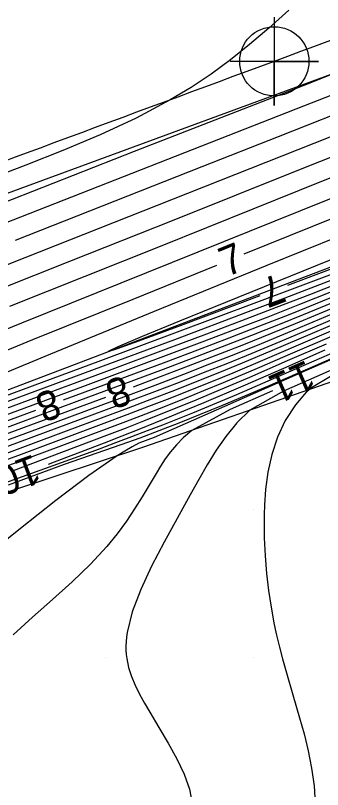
# Model space of a CAD drawing. Extents: x 2602990 to 2605851, y 618069 to 619180.
# Drawn here: x 2603323.9 to 2603344.7, y 618361.1 to 618413.5 of the extents above; entities that cross this region are included whole.
import ezdxf

# ---------------------------------------------------------------- set-up
doc = ezdxf.new("R2010")
doc.units = 0
for name, color, linetype in [('DTM Contours Major', 7, 'Continuous'), ('DTM Contours Major Text', 7, 'Continuous'), ('DTM Contours Minor', 7, 'Continuous'), ('DTM Contours Minor Text', 7, 'Continuous'), ('Exist DTM Breakline', 7, 'Continuous'), ('Exist DTM Crownline', 7, 'Continuous'), ('Exist DTM Drainline', 7, 'Continuous'), ('Exist DTM QL2 LIDAR Elevation Point', 7, 'Continuous'), ('Exist Roads EOP', 7, 'Continuous'), ('Exist Roads EOP Cogo Point CELL', 7, 'Continuous'), ('PH Exist DTM Breakline', 7, 'Continuous')]:
    doc.layers.add(name, color=color, linetype=linetype)

# ---------------------------------------------------------------- blocks, each defined once
blk = doc.blocks.new('EXIST ROADS EOP COGO POINT')
at = {"layer": 'Exist Roads EOP Cogo Point CELL'}
blk.add_lwpolyline([(0, 0.06), (0, -0.06), (0, 0), (0.06, 0), (-0.06, 0)], dxfattribs=at)
blk.add_circle((0, 0), 0.0469, dxfattribs=at)

msp = doc.modelspace()

# ---------------------------------------------------------------- linework, layer by layer
at = {"layer": 'DTM Contours Major'}
for points in [[(2603413.545, 618431.919), (2603412.996, 618431.681), (2603409.631, 618430.243), (2603406.411, 618428.892), (2603404.635, 618428.163), (2603402.929, 618427.472), (2603397.939, 618425.471), (2603396.224, 618424.775), (2603393.341, 618423.584), (2603390.362, 618422.333), (2603387.382, 618421.067), (2603378.36, 618417.204), (2603374.888, 618415.735), (2603371.983, 618414.523), (2603369.421, 618413.467), (2603366.184, 618412.15), (2603362.493, 618410.666), (2603360.498, 618409.871), (2603355.313, 618407.823), (2603347.349, 618404.69), (2603343.063, 618402.99), (2603334.617, 618399.609), (2603327.541, 618396.809), (2603322.626, 618394.861)], [(2603327.142, 618387.436), (2603329.882, 618388.446), (2603334.103, 618390.016), (2603336.235, 618390.819), (2603338.358, 618391.628), (2603340.454, 618392.438), (2603342.502, 618393.244), (2603345.343, 618394.387), (2603348.24, 618395.558), (2603349.768, 618396.167), (2603351.382, 618396.8), (2603354.411, 618397.96), (2603357.65, 618399.168), (2603360.984, 618400.389), (2603364.298, 618401.584), (2603367.476, 618402.714), (2603370.402, 618403.744), (2603377.465, 618406.199), (2603378.885, 618406.7)], [(2603321.928, 618381.394), (2603325.861, 618382.792), (2603329.565, 618384.129), (2603330.69, 618384.544), (2603331.775, 618384.95), (2603332.828, 618385.351), (2603333.862, 618385.751), (2603334.885, 618386.155), (2603335.909, 618386.567), (2603338.881, 618387.801), (2603341.899, 618389.097), (2603347.922, 618391.734)], [(2603232.042, 618350.596), (2603232.796, 618350.941), (2603234.02, 618351.488), (2603235.249, 618352.027), (2603236.484, 618352.559), (2603237.724, 618353.086), (2603240.316, 618354.172), (2603243.023, 618355.288), (2603245.739, 618356.391), (2603248.557, 618357.518), (2603251.681, 618358.75), (2603259.068, 618361.639), (2603269.134, 618365.569), (2603283.544, 618371.218), (2603285.941, 618372.151), (2603288.321, 618373.072), (2603290.658, 618373.969), (2603292.932, 618374.831), (2603294.547, 618375.436), (2603297.726, 618376.612), (2603305.437, 618379.437), (2603325.265, 618386.744)]]:
    msp.add_lwpolyline(points, dxfattribs=at)
at = {"layer": 'DTM Contours Minor'}
for points in [[(2603403.118, 618431.883), (2603402.833, 618431.716), (2603401.509, 618431.051), (2603400.138, 618430.437), (2603398.705, 618429.837), (2603396.601, 618428.974), (2603389.756, 618426.194), (2603387.413, 618425.235), (2603385.098, 618424.275), (2603383.059, 618423.417), (2603381.096, 618422.58), (2603379.234, 618421.777), (2603375.917, 618420.331), (2603372.342, 618418.768), (2603370.744, 618418.086), (2603369.125, 618417.415), (2603367.476, 618416.749), (2603366.161, 618416.225), (2603363.212, 618415.062), (2603355.846, 618412.179), (2603342.883, 618407.119), (2603323.073, 618399.352)], [(2603404.805, 618429.792), (2603402.356, 618428.763), (2603397.015, 618426.54), (2603393.763, 618425.171), (2603390.363, 618423.726), (2603383.658, 618420.855), (2603377.118, 618418.051), (2603373.608, 618416.562), (2603370.947, 618415.449), (2603368.133, 618414.295), (2603365.49, 618413.229), (2603362.398, 618411.996), (2603356.695, 618409.75), (2603347.476, 618406.133), (2603343.027, 618404.375), (2603335.553, 618401.401), (2603324.512, 618397.047), (2603321.717, 618395.941)], [(2603420.115, 618429.811), (2603414.444, 618427.466), (2603412.4, 618426.631), (2603410.273, 618425.78), (2603407.575, 618424.729), (2603404.796, 618423.669), (2603399.182, 618421.553), (2603396.445, 618420.513), (2603393.816, 618419.495), (2603391.861, 618418.719), (2603389.996, 618417.962), (2603388.217, 618417.228), (2603384.894, 618415.834), (2603380.738, 618414.085), (2603376.915, 618412.495), (2603372.47, 618410.663), (2603366.926, 618408.396), (2603360.741, 618405.884), (2603357.67, 618404.644), (2603353.114, 618402.816), (2603345.544, 618399.793), (2603340.999, 618397.957), (2603339.355, 618397.29)], [(2603419.344, 618427.828), (2603414.878, 618426.042), (2603413.257, 618425.399), (2603411.538, 618424.727), (2603408.592, 618423.6), (2603405.452, 618422.42), (2603399.003, 618420.016), (2603395.902, 618418.85), (2603393.023, 618417.746), (2603391.418, 618417.117), (2603389.917, 618416.517), (2603388.501, 618415.943), (2603385.862, 618414.853), (2603379.015, 618412.007), (2603373.646, 618409.794), (2603366.67, 618406.942), (2603359.531, 618404.041), (2603352.87, 618401.348), (2603345.847, 618398.525), (2603340.928, 618396.532), (2603333.274, 618393.41), (2603325.868, 618390.375), (2603313.612, 618385.304)], [(2603417.517, 618425.453), (2603414.066, 618424.14), (2603412.789, 618423.658), (2603409.595, 618422.466), (2603398.796, 618418.475), (2603395.337, 618417.183), (2603392.219, 618416), (2603391, 618415.528), (2603388.789, 618414.656), (2603386.781, 618413.846), (2603382.843, 618412.232), (2603374.157, 618408.651), (2603367.059, 618405.748), (2603358.865, 618402.415), (2603348.621, 618398.269), (2603338.121, 618394.025), (2603335.008, 618392.758), (2603332.478, 618391.718), (2603330.78, 618391.004), (2603330.166, 618390.713), (2603330.794, 618390.91), (2603332.502, 618391.528), (2603335.058, 618392.477), (2603340.472, 618394.503)], [(2603290.205, 618375.323), (2603291.172, 618375.7), (2603294.664, 618377.053), (2603299.329, 618378.84), (2603301.718, 618379.745), (2603305.614, 618381.208), (2603309.652, 618382.713), (2603313.719, 618384.22), (2603329.659, 618390.101), (2603334.868, 618392.036), (2603342.845, 618395.018), (2603349.595, 618397.548), (2603354.049, 618399.193), (2603357.917, 618400.605), (2603361.91, 618402.052), (2603365.862, 618403.476), (2603369.608, 618404.82), (2603380.777, 618408.802), (2603385.235, 618410.41), (2603388.763, 618411.704), (2603393.297, 618413.38), (2603399.856, 618415.829), (2603421.294, 618423.877)], [(2603342.346, 618395.203), (2603346.74, 618396.847), (2603349.221, 618397.769), (2603353.79, 618399.451), (2603358.304, 618401.098), (2603362.673, 618402.68), (2603366.805, 618404.166), (2603373.987, 618406.733), (2603380.77, 618409.151), (2603385.418, 618410.826), (2603388.674, 618412.017), (2603392.382, 618413.39), (2603399.188, 618415.936), (2603411.378, 618420.524), (2603420.72, 618424.055)], [(2603313.054, 618383.538), (2603329.838, 618389.732), (2603334.678, 618391.531), (2603339.689, 618393.409), (2603342.171, 618394.347), (2603346.586, 618396.033), (2603349.67, 618397.21), (2603350.771, 618397.626), (2603354.149, 618398.885), (2603357.825, 618400.235), (2603361.637, 618401.621), (2603365.425, 618402.986), (2603369.026, 618404.275), (2603374.166, 618406.1), (2603379.131, 618407.858), (2603382.195, 618408.957), (2603385.008, 618409.977), (2603388.356, 618411.209), (2603394.207, 618413.366), (2603397.184, 618414.473), (2603415.908, 618421.475)], [(2603315.864, 618384.142), (2603329.882, 618389.314), (2603334.484, 618391.024), (2603336.858, 618391.914), (2603339.233, 618392.811), (2603341.576, 618393.703), (2603343.851, 618394.58), (2603348.482, 618396.388), (2603350.993, 618397.355), (2603354.232, 618398.574), (2603357.751, 618399.874), (2603361.4, 618401.203), (2603365.029, 618402.512), (2603368.489, 618403.748), (2603372.728, 618405.247), (2603377.537, 618406.937), (2603380.566, 618408.015), (2603383.427, 618409.047), (2603386.036, 618410.004), (2603390.363, 618411.608), (2603395.133, 618413.359), (2603398.065, 618414.445), (2603411.959, 618419.632), (2603416.921, 618421.474)], [(2603380.805, 618415.486), (2603377.358, 618414.039), (2603373.024, 618412.243), (2603369.671, 618410.866), (2603364.659, 618408.825), (2603359.3, 618406.66), (2603354.671, 618404.81), (2603347.142, 618401.824), (2603343.198, 618400.245), (2603332.764, 618396.031), (2603324.278, 618392.634), (2603322.422, 618391.886)], [(2603377.805, 618415.596), (2603376.515, 618415.052), (2603372.497, 618413.38), (2603369.54, 618412.164), (2603365.443, 618410.495), (2603360.917, 618408.671), (2603358.577, 618407.737), (2603353.996, 618405.922), (2603347.242, 618403.255), (2603343.12, 618401.613), (2603333.689, 618397.82), (2603323.48, 618393.759)], [(2603365.922, 618414.765), (2603365.384, 618414.55), (2603361.367, 618412.964), (2603347.631, 618407.585), (2603341.685, 618405.245), (2603336.517, 618403.202), (2603323.851, 618398.222)], [(2603342.419, 618413.827), (2603341.064, 618412.608), (2603339.751, 618411.488), (2603338.453, 618410.454), (2603337.142, 618409.493), (2603335.793, 618408.593), (2603334.376, 618407.74), (2603332.071, 618406.519), (2603329.621, 618405.376), (2603327.099, 618404.309), (2603324.577, 618403.317), (2603322.127, 618402.396)], [(2603347.158, 618410.217), (2603346.255, 618409.847), (2603344.289, 618409.057), (2603342.462, 618408.338), (2603331.935, 618404.24), (2603319.49, 618399.375)], [(2603321.359, 618384.871), (2603328.055, 618387.337), (2603331.893, 618388.759), (2603333.912, 618389.514), (2603335.927, 618390.274), (2603337.926, 618391.039), (2603339.904, 618391.809), (2603341.851, 618392.582), (2603343.402, 618393.21), (2603348.131, 618395.148), (2603349.808, 618395.825), (2603351.574, 618396.525), (2603354.508, 618397.656), (2603357.613, 618398.82), (2603360.792, 618399.986), (2603363.948, 618401.124), (2603366.984, 618402.203), (2603369.804, 618403.192), (2603377.41, 618405.823), (2603378.785, 618406.306)], [(2603331.886, 618388.324), (2603333.72, 618389.011), (2603335.617, 618389.73), (2603337.496, 618390.452), (2603339.358, 618391.181), (2603341.204, 618391.92), (2603342.879, 618392.606), (2603348.031, 618394.742), (2603349.857, 618395.487), (2603351.771, 618396.252), (2603354.61, 618397.353), (2603357.58, 618398.471), (2603360.604, 618399.584), (2603363.602, 618400.665), (2603366.498, 618401.693), (2603369.211, 618402.641), (2603373.538, 618404.13), (2603376.116, 618405.015), (2603377.351, 618405.444), (2603378.683, 618405.911)], [(2603307.387, 618378.871), (2603325.442, 618385.504), (2603329.87, 618387.141), (2603331.717, 618387.829), (2603333.526, 618388.509), (2603335.305, 618389.186), (2603337.065, 618389.866), (2603338.814, 618390.555), (2603340.561, 618391.259), (2603342.358, 618392.001), (2603347.941, 618394.34), (2603349.916, 618395.154), (2603351.972, 618395.982), (2603354.713, 618397.051), (2603357.549, 618398.123), (2603360.418, 618399.181), (2603363.261, 618400.207), (2603366.015, 618401.183), (2603368.621, 618402.092), (2603371.763, 618403.171), (2603375.976, 618404.61), (2603377.289, 618405.064), (2603378.581, 618405.517)], [(2603321.931, 618383.339), (2603327.334, 618385.332), (2603329.882, 618386.28), (2603331.534, 618386.9), (2603333.126, 618387.503), (2603334.677, 618388.099), (2603336.206, 618388.697), (2603337.733, 618389.307), (2603339.277, 618389.937), (2603341.318, 618390.791), (2603347.794, 618393.55), (2603350.066, 618394.5), (2603352.392, 618395.449), (2603354.925, 618396.447), (2603357.488, 618397.424), (2603360.051, 618398.375), (2603362.585, 618399.291), (2603365.059, 618400.166), (2603367.444, 618400.994), (2603370.938, 618402.186), (2603375.696, 618403.798), (2603377.167, 618404.304), (2603378.379, 618404.728)], [(2603322.547, 618384.004), (2603327.504, 618385.83), (2603331.627, 618387.364), (2603333.328, 618388.006), (2603334.992, 618388.642), (2603336.635, 618389.281), (2603338.272, 618389.93), (2603339.919, 618390.598), (2603341.837, 618391.396), (2603347.862, 618393.942), (2603349.986, 618394.824), (2603352.179, 618395.714), (2603354.819, 618396.749), (2603357.519, 618397.774), (2603360.235, 618398.778), (2603362.922, 618399.749), (2603365.536, 618400.675), (2603368.032, 618401.543), (2603371.353, 618402.679), (2603374.766, 618403.84)], [(2603301.107, 618378.27), (2603328.447, 618388.349), (2603332.064, 618389.689), (2603334.292, 618390.52), (2603336.545, 618391.365), (2603338.793, 618392.218), (2603341.009, 618393.068), (2603343.165, 618393.909), (2603348.357, 618395.971), (2603349.736, 618396.513), (2603351.19, 618397.078), (2603354.319, 618398.266), (2603357.695, 618399.519), (2603361.185, 618400.794), (2603363.976, 618401.8)], [(2603320.713, 618382.011), (2603323.918, 618383.19), (2603327.021, 618384.341), (2603329.923, 618385.43), (2603331.352, 618385.972), (2603332.719, 618386.497), (2603334.044, 618387.014), (2603335.35, 618387.532), (2603336.659, 618388.062), (2603337.991, 618388.612), (2603340.291, 618389.585), (2603342.692, 618390.618), (2603345.171, 618391.692), (2603347.704, 618392.782), (2603350.267, 618393.868), (2603352.837, 618394.927), (2603355.141, 618395.843), (2603357.426, 618396.722), (2603359.687, 618397.564), (2603361.917, 618398.373), (2603362.83, 618398.696)], [(2603337.502, 618396.538), (2603331.831, 618394.237), (2603325.031, 618391.49), (2603320.312, 618389.566)], [(2603318.338, 618381.583), (2603324.287, 618383.768), (2603327.172, 618384.835), (2603329.897, 618385.853), (2603331.442, 618386.435), (2603332.923, 618387), (2603334.361, 618387.556), (2603335.778, 618388.114), (2603337.195, 618388.684), (2603338.635, 618389.275), (2603340.802, 618390.187), (2603347.551, 618393.081)], [(2603347.449, 618391.17), (2603344.196, 618389.749), (2603340.97, 618388.349), (2603337.86, 618387.03), (2603334.954, 618385.85), (2603333.606, 618385.331), (2603332.306, 618384.85), (2603331.028, 618384.394), (2603327.171, 618383.063), (2603323.381, 618381.665)], [(2603323.751, 618382.66), (2603327.028, 618383.885), (2603330.061, 618385.037), (2603331.342, 618385.531), (2603332.571, 618386.01), (2603333.766, 618386.482), (2603334.947, 618386.957), (2603336.133, 618387.442), (2603337.344, 618387.946), (2603339.777, 618388.982), (2603342.334, 618390.09), (2603344.978, 618391.24)], [(2603346.968, 618390.891), (2603343.587, 618389.422), (2603333.278, 618384.888), (2603332.25, 618384.506), (2603331.784, 618384.253), (2603331.292, 618383.965), (2603330.774, 618383.641), (2603328.846, 618382.305), (2603326.623, 618380.625), (2603324.222, 618378.734), (2603321.762, 618376.765)], [(2603326.107, 618383.088), (2603326.517, 618383.241), (2603329.907, 618384.538), (2603331.105, 618385.004), (2603332.255, 618385.457), (2603333.371, 618385.904), (2603334.471, 618386.35), (2603335.568, 618386.802), (2603336.68, 618387.267), (2603339.319, 618388.395), (2603342.07, 618389.592), (2603344.891, 618390.827)], [(2603347.353, 618390.345), (2603342.064, 618388.015), (2603339.78, 618386.735), (2603338.897, 618385.87), (2603338.139, 618384.966), (2603337.476, 618384.024), (2603336.875, 618383.048), (2603336.305, 618382.039), (2603335.735, 618380.998), (2603334.851, 618379.412), (2603333.955, 618377.795), (2603333.108, 618376.181), (2603332.368, 618374.603), (2603331.795, 618373.094), (2603331.447, 618371.687), (2603331.405, 618371.379), (2603331.378, 618371.077), (2603331.366, 618370.782), (2603331.369, 618370.491), (2603331.388, 618370.206), (2603331.421, 618369.924), (2603331.548, 618369.31), (2603331.74, 618368.708), (2603331.988, 618368.11), (2603332.283, 618367.51), (2603332.618, 618366.904), (2603332.983, 618366.283), (2603333.603, 618365.257), (2603334.231, 618364.203), (2603334.817, 618363.142), (2603335.314, 618362.095), (2603335.674, 618361.085), (2603335.849, 618360.133)], [(2603345.463, 618389.143), (2603343.73, 618388.105), (2603342.863, 618387.104), (2603342.176, 618386.03), (2603341.648, 618384.901), (2603341.261, 618383.735), (2603340.996, 618382.549), (2603340.833, 618381.362), (2603340.802, 618381.019), (2603340.777, 618380.677), (2603340.759, 618380.336), (2603340.737, 618379.653), (2603340.733, 618379.312), (2603340.749, 618378.095), (2603340.809, 618376.882), (2603340.908, 618375.685), (2603341.042, 618374.521), (2603341.207, 618373.404), (2603341.398, 618372.348), (2603341.487, 618371.918), (2603341.579, 618371.499), (2603341.775, 618370.688), (2603341.984, 618369.898), (2603342.25, 618368.948), (2603342.682, 618367.472), (2603343.144, 618365.915), (2603343.449, 618364.821), (2603343.729, 618363.681), (2603343.961, 618362.509), (2603344.123, 618361.315), (2603344.192, 618360.111)], [(2603341.312, 618388.053), (2603338.429, 618386.784), (2603335.83, 618385.365), (2603335.272, 618384.878), (2603334.798, 618384.396), (2603334.391, 618383.915), (2603334.034, 618383.434), (2603333.712, 618382.948), (2603333.408, 618382.457), (2603332.461, 618380.87), (2603331.951, 618380.049), (2603331.395, 618379.213), (2603330.775, 618378.365), (2603330.074, 618377.508), (2603328.961, 618376.316), (2603327.715, 618375.117), (2603326.389, 618373.914), (2603325.039, 618372.713), (2603323.716, 618371.521)], [(2603307.693, 618379.411), (2603327.865, 618386.833), (2603330.011, 618387.629)]]:
    msp.add_lwpolyline(points, dxfattribs=at)
at = {"layer": 'Exist DTM Breakline'}
msp.add_lwpolyline([(2603537.954, 618480.779), (2603486.109, 618461.906), (2603428.704, 618440.722), (2603369.241, 618418.295), (2603303.922, 618394.289), (2603246.763, 618372.687), (2603198.271, 618355.074)], dxfattribs=at)
at = {"layer": 'Exist DTM Crownline'}
msp.add_spline([(2603233.488, 618380.754), (2603285.185, 618400.095), (2603335.457, 618418.629), (2603390.812, 618439.069), (2603440.087, 618457.325), (2603493.996, 618477.231), (2603542.655, 618495.301), (2603600.808, 618516.867), (2603653.659, 618536.362), (2603706.222, 618555.742), (2603764.811, 618577.593), (2603823.52, 618599.847), (2603878.564, 618620.56), (2603937.951, 618643.078), (2603997.369, 618665.789), (2604036.209, 618680.665), (2604055.311, 618688.017)], degree=3, dxfattribs=at)
at = {"layer": 'Exist DTM Drainline'}
msp.add_lwpolyline([(2603204.098, 618342.063), (2603247.886, 618359.31), (2603300.002, 618379.256), (2603348.063, 618397.511), (2603388.725, 618412.554), (2603432.793, 618429.056), (2603474.09, 618444.074), (2603510.151, 618459.891), (2603545.952, 618474.924)], dxfattribs=at)
at = {"layer": 'Exist DTM QL2 LIDAR Elevation Point'}
for p, q in [((2603340, 618380), (2603340, 618380)), ((2603330, 618370), (2603330, 618370)), ((2603340, 618370), (2603340, 618370))]:
    msp.add_line(p, q, dxfattribs=at)
at = {"layer": 'Exist Roads EOP'}
for points in [[(2603230.17, 618389.98), (2603282.929, 618409.597), (2603332.773, 618427.868), (2603388.167, 618448.413), (2603437.203, 618466.721), (2603490.778, 618486.527), (2603539.039, 618504.558), (2603597.451, 618526.156), (2603651.053, 618545.972), (2603705.208, 618566.084), (2603762.02, 618587.183), (2603820.334, 618609.162), (2603876.341, 618629.99), (2603934.909, 618652.28), (2603996.409, 618675.568), (2604033.216, 618689.957), (2604052.01, 618697.199)], [(2604034.633, 618668.486), (2603984.89, 618650.123), (2603936.767, 618631.654), (2603888.195, 618613.335), (2603837.766, 618594.258), (2603782.918, 618573.705), (2603731.939, 618554.39), (2603671.126, 618532.171), (2603621.822, 618514.106), (2603561.545, 618491.877), (2603506.421, 618471.293), (2603452.163, 618451.33), (2603398.364, 618431.316), (2603341.431, 618410.355), (2603281.65, 618388.199), (2603223.033, 618366.475), (2603185.717, 618352.612)]]:
    msp.add_spline(points, degree=3, dxfattribs=at)
at = {"layer": 'PH Exist DTM Breakline'}
msp.add_lwpolyline([(2603546.278, 618467.89), (2603526.855, 618460.306), (2603507.213, 618451.651), (2603485.725, 618442.619), (2603466.383, 618433.876), (2603454.696, 618429.386), (2603442.234, 618424.385), (2603428.822, 618418.102), (2603416.965, 618413.956), (2603393.207, 618405.535), (2603378.639, 618399.772), (2603357.505, 618392.883), (2603332.502, 618384.211), (2603305.954, 618375.46), (2603282.242, 618367.811), (2603247.909, 618354.209), (2603229.683, 618345.761), (2603219.668, 618341.177), (2603212.41, 618339.282), (2603206.143, 618338.068)], dxfattribs=at)

# ---------------------------------------------------------------- block references
at = {"layer": 'Exist Roads EOP Cogo Point CELL', "xscale": 50, "yscale": 50}
msp.add_blockref('EXIST ROADS EOP COGO POINT', (2603341.431, 618410.355), dxfattribs=at)

# ---------------------------------------------------------------- texts
at = {"layer": 'DTM Contours Major Text'}
msp.add_text('8', height=2, rotation=200.2308, dxfattribs=at).set_placement((2603326.471, 618388.254))
at = {"layer": 'DTM Contours Minor Text'}
for s, rotation, p in [('7', 22.091, (2603338.199, 618395.742)), ('7', 200.5125, (2603341.671, 618396.019)), ('11', 203.7523, (2603343.619, 618390.161)), ('8', 200.3553, (2603331.214, 618389.141)), ('10', 200.4268, (2603325.102, 618383.779))]:
    msp.add_text(s, height=2, rotation=rotation, dxfattribs=at).set_placement(p)

doc.saveas('drawing.dxf')
